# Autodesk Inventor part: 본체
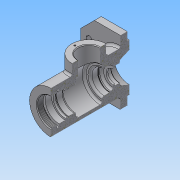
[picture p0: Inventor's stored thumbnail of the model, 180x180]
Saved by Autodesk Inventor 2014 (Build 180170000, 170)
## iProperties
Created: 2017-10
Part Number: 본체
Material: 일반
Document SubType Name: Modeling
Designer: NET
Density: 1 g/cm^3
Appearance: 기본값
Author: NET
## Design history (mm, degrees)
sketch "스케치1"
  geometry: L1 (-51, 0)-(51, 0); L2 (51, 0)-(51, 31); L3 (51, 31)-(-51, 31); L4 (-51, 31)-(-51, 0); 2 further points
  constraints: 8 end point, 3 perpendicular, 1 coincident, 1 horizontal, 1 midpoint
  dimensions: "d0" = 102 distance of L1.start L1.end; "d1" = 62 diameter of L3 L1
revolve "회전1" sketch "스케치1" stored, may be unused: angle "d2" = 90 deg
node "작업 평면1"
sketch "스케치2"
  geometry: L1 (31, -51)-(-31, -51) reference; L2 (31, 51)-(-31, 51) reference; C1 r 25 at (0, 5); 1 further point
  constraints: 1 centre point, 1 vertical alignment
  dimensions: "d4" = 50 diameter of C1; "d5" = 56 distance from line of L1 C1.centre
extrude "돌출1" join sketch "스케치2" stored distance "d6" = 10; taper "d7" = 0 deg
sketch "스케치3"
  geometry: L1 (-58, 47)-(58, 47); L2 (58, 47)-(58, -47); L3 (58, -47)-(-58, -47); L4 (-58, -47)-(-58, 47); C1 r 31 at (0, 0) reference; C2 r 35 at (0, 0); 2 further points
  constraints: 8 end point, 2 midpoint, 2 parallel, 1 centre point, 1 coincident, 1 horizontal, 1 horizontal alignment, 1 perpendicular, 1 vertical alignment
  dimensions: "d8" = 116 distance of L1.start L1.end; "d9" = 94 distance of L1.end L2.end; "d10" = 70 diameter of C2
extrude "돌출2" join sketch "스케치3" distance "d11" = 13; taper "d12" = 0 deg
extrude "돌출3" join sketch "스케치3" distance "d13" = 10; taper "d14" = 0 deg
sketch "스케치4"
  geometry: L1 (58, -47)-(58, 47) reference; L2 (46, -20)-(46, 20); L3 (50, -20)-(50, 20); L4 (42, 20)-(42, -20); L5 (-46, 20)-(-46, -20); L6 (-50, 20)-(-50, -20); L7 (-42, -20)-(-42, 20); C1 r 31 at (0, 0) reference; C2 r 31 at (0, 0) reference; A1 r 4 centre (46, -20) between (42, -20) and (50, -20); A2 r 4 centre (46, 20) between (50, 20) and (42, 20); A3 r 4 centre (-46, 20) between (-42, 20) and (-50, 20); A4 r 4 centre (-46, -20) between (-50, -20) and (-42, -20); 2 further points
  constraints: 16 end point, 8 point on circle, 8 tangent, 5 parallel, 4 centre point, 2 horizontal alignment, 2 midpoint
  dimensions: "d15" = 8 diameter of A2; "d16" = 8 diameter of A4; "d17" = 40 distance of L3.start L3.end; "d18" = 92 distance between parallel lines of L2 L5; "d19" = 46 distance of point (-46, 0) C1.centre
extrude "돌출4" cut sketch "스케치4" stored distance "d20" = 10; taper "d21" = 0 deg
sketch "스케치5"
  geometry: L1 (-51, -31)-(-51, 31) reference; L2 (64, -35)-(64, 35) reference; L3 (-51, 0)-(64, 0); L4 (-42, 0)-(-42, 24); L5 (-42, 24)-(-39, 24); L6 (-39, 24)-(-39, 20); L7 (-39, 20)-(-30, 20); L8 (-30, 20)-(-30, 17.5); L9 (-30, 17.5)-(-26.75, 17.5); L10 (-26.75, 17.5)-(-26.75, 18.5); L11 (-26.75, 18.5)-(-25, 18.5); L12 (-25, 18.5)-(-25, 17.5); L13 (-25, 17.5)-(-14, 17.5); L14 (-14, 17.5)-(-14, 26); L15 (-14, 26)-(24, 26); L16 (24, 26)-(24, 17.5); L17 (24, 17.5)-(35, 17.5); L18 (35, 17.5)-(35, 16.5); L19 (35, 16.5)-(40, 16.5); L20 (40, 16.5)-(40, 10); L21 (40, 10)-(42.7, 10); L22 (42.7, 10)-(42.7, 12.5); L23 (42.7, 12.5)-(49.3, 12.5); L24 (64, 0)-(64, 22); L25 (50, 12.904)-(50, 16); L26 (50, 16)-(64, 22); L27 (49.3, 12.5)-(50, 12.904); 2 further points
  constraints: 50 end point, 16 parallel, 3 perpendicular, 3 point on line, 2 collinear, 2 midpoint, 1 horizontal
  dimensions: "d27" = 38 distance of L14.end L15.end; "d28" = 60 distance between parallel lines of L18 L12; "d29" = 5 distance between parallel lines of L20 L18; "d30" = 2.7 distance between parallel lines of L22 L20; "d32" = 35 diameter of L13 L3; "d33" = 52 diameter of L15 L3; "d34" = 40 diameter of L7 L3; "d35" = 35 diameter of L9 L3; "d36" = 37 diameter of L11 L3; "d37" = 48 diameter of L5 L3; "d38" = 11 distance of L12.end L13.end; "d39" = 20 diameter of L21 L3; "d41" = 33 diameter of L19 L3; "d42" = 1.75 distance of L10.end L11.end; "d43" = 21 distance between parallel lines of L8 L1; "d44" = 9 distance between parallel lines of L4 L1; "d45" = 12 distance between parallel lines of L6 L1; "d46" = 26 distance between parallel lines of L12 L1; "d62" = 25 diameter of L23 L3; "d63" = 44 diameter of L24.end L3; "d64" = 32 diameter of L25.end L3; "d65" = 14 distance between parallel lines of L2 L25; "d75" = 30 deg angle of L27 L23; "d76" = 0.7 horizontal distance of L25.start L23.end
revolve "회전2" sketch "스케치5" stored, may be unused: angle "d47" = 90 deg
hole "구멍1" diameter "d50" = 32; stored, may be unused: countersink angle "d54" = 90 deg, drill point angle "d56" = 118 deg; dims "d51" = 6, "d52" = 4, "d53" = 2, "d55" = 8, "d57" = 10, "d58" = 10
sketch "스케치6"
  geometry: C1 r 16 at (0, 0) reference; 3 further points
  constraints: 2 horizontal alignment
  dimensions: "d59" = 41 distance of point (20.5, 0) point (-20.5, 0); "d60" = 20.5 distance of point (-20.5, 0) C1.centre
node "작업 평면2"
sketch "스케치8"
  geometry: L1 (-25, 0)-(25, 0) reference; L2 (-56, -78)-(-56, -16) reference; 2 further points
  constraints: 1 other
  dimensions: "d66" = 10 distance from line of point (0, -10) L1; "d67" = 56 distance from line of point (0, -10) L2
feature "엠보싱1" sketch "스케치8" dims "d0" = 102, "d1" = 62, "d8" = 116, "d9" = 94, "d68" = 0.5, "d69" = 0
chamfer "모따기1" distance "d70" = 20; stored, may be unused: second distance "d71" = 2, angle "d72" = 45 deg
hole "구멍2" sketch "스케치6" diameter "d77" = 2.459; stored, may be unused: countersink angle "d81" = 90 deg, drill point angle "d83" = 118 deg; dims "d78" = 6, "d79" = 4, "d80" = 2, "d82" = 8
hole "구멍3" diameter "d86" = 40.376; stored, may be unused: countersink angle "d90" = 90 deg, drill point angle "d92" = 0 deg; dims "d84" = 10, "d85" = 10, "d87" = 9, "d88" = 4, "d89" = 2, "d91" = 9
fillet "모깎기1" dims "d93" = 0.3
fillet "모깎기2" dims "d94" = 0.3
fillet "모깎기3" dims "d95" = 3
fillet "모깎기4" dims "d96" = 3
chamfer "모따기2" distance "d97" = 1; stored, may be unused: second distance "d98" = 2, angle "d99" = 45 deg
chamfer "모따기3" distance "d100" = 1; stored, may be unused: second distance "d101" = 2, angle "d102" = 45 deg
fillet "모깎기5" dims "d103" = 3
fillet "모깎기6" dims "d104" = 3
sketch "스케치7"
  geometry: C1 r 12.5 at (0, 0) reference; C2 r 35 at (0, 0) reference
node "솔리드1"
node "투영된 루프1"
node "투영된 루프2"
other parameters: "d3" = 47
